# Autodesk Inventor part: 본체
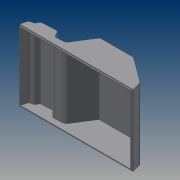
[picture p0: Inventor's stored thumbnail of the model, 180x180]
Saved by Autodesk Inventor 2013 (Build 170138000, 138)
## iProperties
Created: 2015-05
Part Number: 본체
Material: 일반
Document SubType Name: Modeling
Designer: Administrator
Density: 1 g/cm^3
Author: Administrator
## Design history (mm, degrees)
sketch "스케치1"
  geometry: L1 (-61, 0)-(61, 0); L2 (-3.271, 31)-(30.011, 31); L3 (58.324, 9.987)-(61, 0); L4 (-61, 0)-(-59.132, 6.971); L5 (-52.531, 11.511)-(-52.429, 11.895); L6 (-49.688, 14.114)-(-35.768, 14.844); L7 (-32.849, 13.02)-(-31.488, 9.812); L8 (-28.569, 7.989)-(-20.56, 8.408); L9 (-18.172, 9.815)-(-5.815, 29.59); L10 (57.21, 11.623)-(31.795, 30.412); L11 (-56.496, 9.183)-(-55.168, 9.299); A1 r 3 centre (-56.234, 6.194) between (-56.496, 9.183) and (-59.132, 6.971); A2 r 3 centre (-49.531, 11.118) between (-49.688, 14.114) and (-52.429, 11.895); A3 r 3 centre (-55.429, 12.288) between (-55.168, 9.299) and (-52.531, 11.511); A4 r 3 centre (-35.611, 11.848) between (-32.849, 13.02) and (-35.768, 14.844); A5 r 3 centre (-28.726, 10.985) between (-31.488, 9.812) and (-28.569, 7.989); A6 r 3 centre (-20.717, 11.404) between (-20.56, 8.408) and (-18.172, 9.815); A7 r 3 centre (-3.271, 28) between (-3.271, 31) and (-5.815, 29.59); A8 r 3 centre (30.011, 28) between (31.795, 30.412) and (30.011, 31); A9 r 3 centre (55.426, 9.211) between (58.324, 9.987) and (57.21, 11.623); 11 further points
  constraints: 22 end point, 18 point on circle, 18 point on line, 18 tangent, 9 centre point, 8 equal radius, 3 parallel, 1 coincident, 1 horizontal, 1 midpoint
  dimensions: "d0" = 122 distance of L1.start L1.end; "d3" = 42 horizontal distance of point (-19, 8.49) L1.start; "d4" = 31 distance between parallel lines of L2 L1; "d5" = 20 distance from line of point (58.053, 11) L2; "d6" = 105 deg angle of L1 L3; "d7" = 105 deg angle of L1 L4; "d8" = 70 deg angle of L5 L11; "d9" = 70 deg angle of L8 L7; "d10" = 125 deg angle of L9 L8; "d12" = 30 horizontal distance of point (31, 31) L1.end; "d13" = 3 deg angle of L8 L1; "d14" = 9 distance from line of L1 point (-58.588, 9); "d15" = 5 vertical distance of point (-51.865, 14) point (-58.588, 9); "d16" = 20 distance from line of point (-53.075, 9.482) L7; "d17" = 31 distance from line of L1.start L7; "d18" = 50 horizontal distance of point (31, 31) point (-19, 8.49) (derived); "d19" = 7.22232 distance between parallel lines of L8 L6; "d22" = 3 radius of A1
extrude "돌출1" new body sketch "스케치1" stored distance "d20" = 76; taper "d21" = 0 deg
feature "쉘1" dims "d23" = 2
sketch "스케치2"
  geometry: L1 (119.929, -2)-(119.929, -74) reference; L2 (119.929, -74)-(2.071, -74) reference; L3 (2.071, -74)-(2.071, -2) reference; L4 (2.071, -2)-(119.929, -2) reference; L5 (122, -76)-(122, 0) reference; L6 (0, 0)-(122, 0) reference; L7 (0, 0)-(0, -76) reference; L8 (122, -76)-(0, -76) reference; L9 (120.929, -1)-(120.929, -75); L10 (120.929, -75)-(1.071, -75); L11 (1.071, -75)-(1.071, -1); L12 (1.071, -1)-(120.929, -1); 1 further point
  constraints: 8 end point, 3 other
  dimensions: "d24" = 1 distance between parallel lines of L12 L6
extrude "돌출2" cut sketch "스케치2" distance "d25" = 1; taper "d26" = 0 deg
node "솔리드1"
